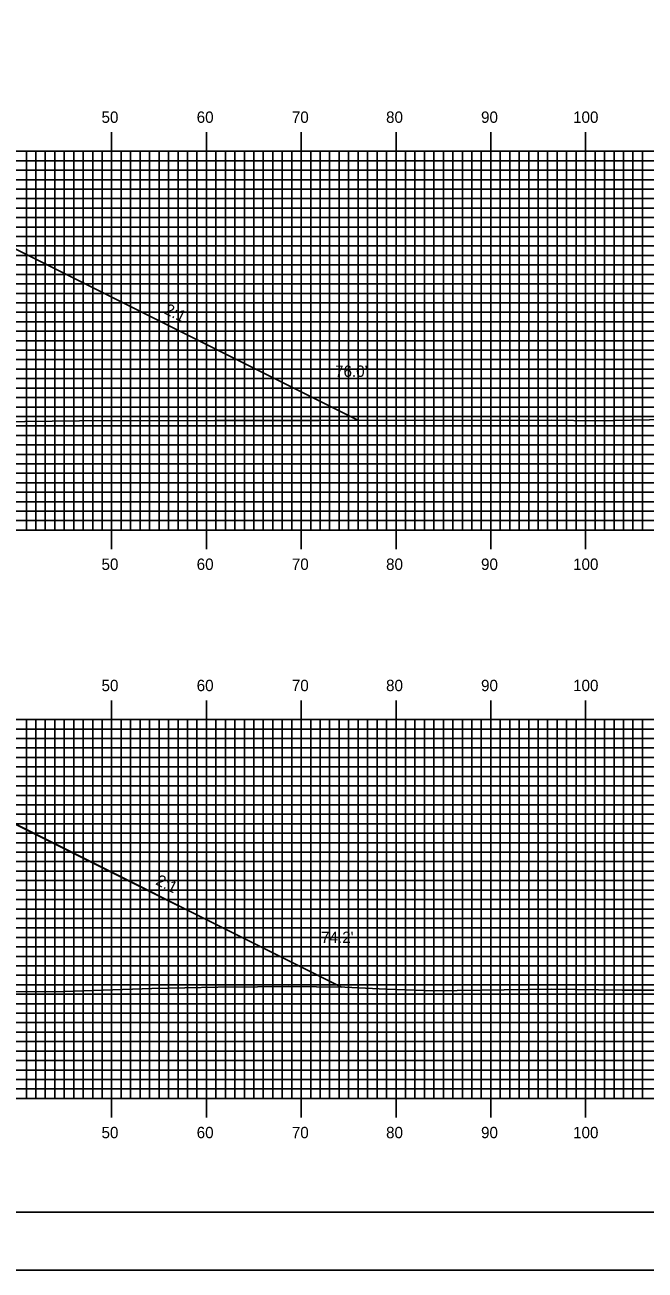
# Model space of a CAD drawing. Extents: x 1759036 to 1759380, y 442591 to 442811.
# Drawn here: x 1759243 to 1759308.4, y 442590.5 to 442722 of the extents above; entities that cross this region are included whole.
import ezdxf

# ---------------------------------------------------------------- set-up
doc = ezdxf.new("R2010")
doc.units = 0
for name, color, linetype in [('ANNOTATION', 7, 'Continuous'), ('BORDER', 7, 'Continuous'), ('D_Roadway_Centerline', 7, 'Continuous'), ('D_Roadway_SlopeLines', 7, 'Continuous'), ('D_Text_Standard', 7, 'Continuous'), ('H_V ANNOTATION', 7, 'Continuous'), ('MAJOR', 7, 'Continuous'), ('MINOR', 7, 'Continuous'), ('PLOT BOUNDARY', 7, 'Continuous'), ('S_Roadway_Centerline', 7, 'Continuous')]:
    doc.layers.add(name, color=color, linetype=linetype)

msp = doc.modelspace()

# ---------------------------------------------------------------- linework, layer by layer
at = {"layer": 'BORDER'}
msp.add_lwpolyline([(1759052.56, 442596.67), (1759372.56, 442596.67), (1759372.56, 442806.67), (1759052.56, 442806.67)], close=True, dxfattribs=at)
at = {"layer": 'D_Roadway_Centerline'}
for points in [[(1759138.72, 442679.79), (1759172.85, 442696.86), (1759178.14, 442699.51), (1759181.14, 442699.63), (1759189.14, 442699.95), (1759190.16, 442699.98), (1759202.16, 442700.41), (1759214.16, 442700.85), (1759226.16, 442701.21), (1759234.16, 442700.89), (1759237.16, 442700.77), (1759241.91, 442698.4), (1759278.21, 442680.25)], [(1759138.26, 442619.99), (1759170.85, 442636.29), (1759176.15, 442638.93), (1759179.15, 442639.05), (1759187.15, 442639.37), (1759190.16, 442639.48), (1759202.16, 442639.92), (1759214.16, 442640.35), (1759226.16, 442640.48), (1759234.16, 442640.16), (1759237.16, 442640.04), (1759241.91, 442637.66), (1759276.4, 442620.42)]]:
    msp.add_lwpolyline(points, dxfattribs=at)
at = {"layer": 'D_Roadway_SlopeLines'}
for points in [[(1759237.16, 442700.77), (1759278.21, 442680.25)], [(1759237.16, 442640.04), (1759276.4, 442620.42)]]:
    msp.add_lwpolyline(points, dxfattribs=at)
at = {"layer": 'MAJOR'}
for p, q in [((1759252.16, 442710.67), (1759252.16, 442708.67)), ((1759262.16, 442710.67), (1759262.16, 442708.67)), ((1759272.16, 442710.67), (1759272.16, 442708.67)), ((1759282.16, 442710.67), (1759282.16, 442708.67)), ((1759292.16, 442710.67), (1759292.16, 442708.67)), ((1759302.16, 442710.67), (1759302.16, 442708.67)), ((1759062.16, 442708.67), (1759342.16, 442708.67)), ((1759062.16, 442708.67), (1759342.16, 442708.67)), ((1759252.16, 442668.67), (1759252.16, 442708.67)), ((1759262.16, 442668.67), (1759262.16, 442708.67)), ((1759272.16, 442668.67), (1759272.16, 442708.67)), ((1759282.16, 442668.67), (1759282.16, 442708.67)), ((1759292.16, 442668.67), (1759292.16, 442708.67)), ((1759302.16, 442668.67), (1759302.16, 442708.67)), ((1759062.16, 442703.67), (1759342.16, 442703.67)), ((1759062.16, 442698.67), (1759342.16, 442698.67)), ((1759062.16, 442693.67), (1759342.16, 442693.67)), ((1759062.16, 442688.67), (1759342.16, 442688.67)), ((1759062.16, 442683.67), (1759342.16, 442683.67)), ((1759062.16, 442678.67), (1759342.16, 442678.67)), ((1759062.16, 442673.67), (1759342.16, 442673.67)), ((1759062.16, 442668.67), (1759342.16, 442668.67)), ((1759062.16, 442668.67), (1759342.16, 442668.67)), ((1759252.16, 442666.66), (1759252.16, 442668.67)), ((1759262.16, 442666.66), (1759262.16, 442668.67)), ((1759272.16, 442666.66), (1759272.16, 442668.67)), ((1759282.16, 442666.66), (1759282.16, 442668.67)), ((1759292.16, 442666.66), (1759292.16, 442668.67)), ((1759302.16, 442666.66), (1759302.16, 442668.67)), ((1759252.16, 442650.67), (1759252.16, 442648.67)), ((1759262.16, 442650.67), (1759262.16, 442648.67)), ((1759272.16, 442650.67), (1759272.16, 442648.67)), ((1759282.16, 442650.67), (1759282.16, 442648.67)), ((1759292.16, 442650.67), (1759292.16, 442648.67)), ((1759302.16, 442650.67), (1759302.16, 442648.67)), ((1759062.16, 442648.67), (1759342.16, 442648.67)), ((1759062.16, 442648.67), (1759342.16, 442648.67)), ((1759252.16, 442608.67), (1759252.16, 442648.67)), ((1759262.16, 442608.67), (1759262.16, 442648.67)), ((1759272.16, 442608.67), (1759272.16, 442648.67)), ((1759282.16, 442608.67), (1759282.16, 442648.67)), ((1759292.16, 442608.67), (1759292.16, 442648.67)), ((1759302.16, 442608.67), (1759302.16, 442648.67)), ((1759062.16, 442643.67), (1759342.16, 442643.67)), ((1759062.16, 442638.67), (1759342.16, 442638.67)), ((1759062.16, 442633.67), (1759342.16, 442633.67)), ((1759062.16, 442628.67), (1759342.16, 442628.67)), ((1759062.16, 442623.67), (1759342.16, 442623.67)), ((1759062.16, 442618.67), (1759342.16, 442618.67)), ((1759062.16, 442613.67), (1759342.16, 442613.67)), ((1759062.16, 442608.67), (1759342.16, 442608.67)), ((1759062.16, 442608.67), (1759342.16, 442608.67)), ((1759252.16, 442606.66), (1759252.16, 442608.67)), ((1759262.16, 442606.66), (1759262.16, 442608.67)), ((1759272.16, 442606.66), (1759272.16, 442608.67)), ((1759282.16, 442606.66), (1759282.16, 442608.67)), ((1759292.16, 442606.66), (1759292.16, 442608.67)), ((1759302.16, 442606.66), (1759302.16, 442608.67))]:
    msp.add_line(p, q, dxfattribs=at)
at = {"layer": 'MINOR'}
for p, q in [((1759243.16, 442668.67), (1759243.16, 442708.67)), ((1759244.16, 442668.67), (1759244.16, 442708.67)), ((1759245.16, 442668.67), (1759245.16, 442708.67)), ((1759246.16, 442668.67), (1759246.16, 442708.67)), ((1759247.16, 442668.67), (1759247.16, 442708.67)), ((1759248.16, 442668.67), (1759248.16, 442708.67)), ((1759249.16, 442668.67), (1759249.16, 442708.67)), ((1759250.16, 442668.67), (1759250.16, 442708.67)), ((1759251.16, 442668.67), (1759251.16, 442708.67)), ((1759253.16, 442668.67), (1759253.16, 442708.67)), ((1759254.16, 442668.67), (1759254.16, 442708.67)), ((1759255.16, 442668.67), (1759255.16, 442708.67)), ((1759256.16, 442668.67), (1759256.16, 442708.67)), ((1759257.16, 442668.67), (1759257.16, 442708.67)), ((1759258.16, 442668.67), (1759258.16, 442708.67)), ((1759259.16, 442668.67), (1759259.16, 442708.67)), ((1759260.16, 442668.67), (1759260.16, 442708.67)), ((1759261.16, 442668.67), (1759261.16, 442708.67)), ((1759263.16, 442668.67), (1759263.16, 442708.67)), ((1759264.16, 442668.67), (1759264.16, 442708.67)), ((1759265.16, 442668.67), (1759265.16, 442708.67)), ((1759266.16, 442668.67), (1759266.16, 442708.67)), ((1759267.16, 442668.67), (1759267.16, 442708.67)), ((1759268.16, 442668.67), (1759268.16, 442708.67)), ((1759269.16, 442668.67), (1759269.16, 442708.67)), ((1759270.16, 442668.67), (1759270.16, 442708.67)), ((1759271.16, 442668.67), (1759271.16, 442708.67)), ((1759273.16, 442668.67), (1759273.16, 442708.67)), ((1759274.16, 442668.67), (1759274.16, 442708.67)), ((1759275.16, 442668.67), (1759275.16, 442708.67)), ((1759276.16, 442668.67), (1759276.16, 442708.67)), ((1759277.16, 442668.67), (1759277.16, 442708.67)), ((1759278.16, 442668.67), (1759278.16, 442708.67)), ((1759279.16, 442668.67), (1759279.16, 442708.67)), ((1759280.16, 442668.67), (1759280.16, 442708.67)), ((1759281.16, 442668.67), (1759281.16, 442708.67)), ((1759283.16, 442668.67), (1759283.16, 442708.67)), ((1759284.16, 442668.67), (1759284.16, 442708.67)), ((1759285.16, 442668.67), (1759285.16, 442708.67)), ((1759286.16, 442668.67), (1759286.16, 442708.67)), ((1759287.16, 442668.67), (1759287.16, 442708.67)), ((1759288.16, 442668.67), (1759288.16, 442708.67)), ((1759289.16, 442668.67), (1759289.16, 442708.67)), ((1759290.16, 442668.67), (1759290.16, 442708.67)), ((1759291.16, 442668.67), (1759291.16, 442708.67)), ((1759293.16, 442668.67), (1759293.16, 442708.67)), ((1759294.16, 442668.67), (1759294.16, 442708.67)), ((1759295.16, 442668.67), (1759295.16, 442708.67)), ((1759296.16, 442668.67), (1759296.16, 442708.67)), ((1759297.16, 442668.67), (1759297.16, 442708.67)), ((1759298.16, 442668.67), (1759298.16, 442708.67)), ((1759299.16, 442668.67), (1759299.16, 442708.67)), ((1759300.16, 442668.67), (1759300.16, 442708.67)), ((1759301.16, 442668.67), (1759301.16, 442708.67)), ((1759303.16, 442668.67), (1759303.16, 442708.67)), ((1759304.16, 442668.67), (1759304.16, 442708.67)), ((1759305.16, 442668.67), (1759305.16, 442708.67)), ((1759306.16, 442668.67), (1759306.16, 442708.67)), ((1759307.16, 442668.67), (1759307.16, 442708.67)), ((1759308.16, 442668.67), (1759308.16, 442708.67)), ((1759062.16, 442707.67), (1759342.16, 442707.67)), ((1759062.16, 442706.67), (1759342.16, 442706.67)), ((1759062.16, 442705.67), (1759342.16, 442705.67)), ((1759062.16, 442704.67), (1759342.16, 442704.67)), ((1759062.16, 442702.67), (1759342.16, 442702.67)), ((1759062.16, 442701.67), (1759342.16, 442701.67)), ((1759062.16, 442700.67), (1759342.16, 442700.67)), ((1759062.16, 442699.67), (1759342.16, 442699.67)), ((1759062.16, 442697.67), (1759342.16, 442697.67)), ((1759062.16, 442696.67), (1759342.16, 442696.67)), ((1759062.16, 442695.67), (1759342.16, 442695.67)), ((1759062.16, 442694.67), (1759342.16, 442694.67)), ((1759062.16, 442692.67), (1759342.16, 442692.67)), ((1759062.16, 442691.67), (1759342.16, 442691.67)), ((1759062.16, 442690.67), (1759342.16, 442690.67)), ((1759062.16, 442689.67), (1759342.16, 442689.67)), ((1759062.16, 442687.67), (1759342.16, 442687.67)), ((1759062.16, 442686.67), (1759342.16, 442686.67)), ((1759062.16, 442685.67), (1759342.16, 442685.67)), ((1759062.16, 442684.67), (1759342.16, 442684.67)), ((1759062.16, 442682.67), (1759342.16, 442682.67)), ((1759062.16, 442681.67), (1759342.16, 442681.67)), ((1759062.16, 442680.67), (1759342.16, 442680.67)), ((1759062.16, 442679.67), (1759342.16, 442679.67)), ((1759062.16, 442677.67), (1759342.16, 442677.67)), ((1759062.16, 442676.67), (1759342.16, 442676.67)), ((1759062.16, 442675.67), (1759342.16, 442675.67)), ((1759062.16, 442674.67), (1759342.16, 442674.67)), ((1759062.16, 442672.67), (1759342.16, 442672.67)), ((1759062.16, 442671.67), (1759342.16, 442671.67)), ((1759062.16, 442670.67), (1759342.16, 442670.67)), ((1759062.16, 442669.67), (1759342.16, 442669.67)), ((1759062.16, 442647.67), (1759342.16, 442647.67)), ((1759243.16, 442608.67), (1759243.16, 442648.67)), ((1759244.16, 442608.67), (1759244.16, 442648.67)), ((1759245.16, 442608.67), (1759245.16, 442648.67)), ((1759246.16, 442608.67), (1759246.16, 442648.67)), ((1759247.16, 442608.67), (1759247.16, 442648.67)), ((1759248.16, 442608.67), (1759248.16, 442648.67)), ((1759249.16, 442608.67), (1759249.16, 442648.67)), ((1759250.16, 442608.67), (1759250.16, 442648.67)), ((1759251.16, 442608.67), (1759251.16, 442648.67)), ((1759253.16, 442608.67), (1759253.16, 442648.67)), ((1759254.16, 442608.67), (1759254.16, 442648.67)), ((1759255.16, 442608.67), (1759255.16, 442648.67)), ((1759256.16, 442608.67), (1759256.16, 442648.67)), ((1759257.16, 442608.67), (1759257.16, 442648.67)), ((1759258.16, 442608.67), (1759258.16, 442648.67)), ((1759259.16, 442608.67), (1759259.16, 442648.67)), ((1759260.16, 442608.67), (1759260.16, 442648.67)), ((1759261.16, 442608.67), (1759261.16, 442648.67)), ((1759263.16, 442608.67), (1759263.16, 442648.67)), ((1759264.16, 442608.67), (1759264.16, 442648.67)), ((1759265.16, 442608.67), (1759265.16, 442648.67)), ((1759266.16, 442608.67), (1759266.16, 442648.67)), ((1759267.16, 442608.67), (1759267.16, 442648.67)), ((1759268.16, 442608.67), (1759268.16, 442648.67)), ((1759269.16, 442608.67), (1759269.16, 442648.67)), ((1759270.16, 442608.67), (1759270.16, 442648.67)), ((1759271.16, 442608.67), (1759271.16, 442648.67)), ((1759273.16, 442608.67), (1759273.16, 442648.67)), ((1759274.16, 442608.67), (1759274.16, 442648.67)), ((1759275.16, 442608.67), (1759275.16, 442648.67)), ((1759276.16, 442608.67), (1759276.16, 442648.67)), ((1759277.16, 442608.67), (1759277.16, 442648.67)), ((1759278.16, 442608.67), (1759278.16, 442648.67)), ((1759279.16, 442608.67), (1759279.16, 442648.67)), ((1759280.16, 442608.67), (1759280.16, 442648.67)), ((1759281.16, 442608.67), (1759281.16, 442648.67)), ((1759283.16, 442608.67), (1759283.16, 442648.67)), ((1759284.16, 442608.67), (1759284.16, 442648.67)), ((1759285.16, 442608.67), (1759285.16, 442648.67)), ((1759286.16, 442608.67), (1759286.16, 442648.67)), ((1759287.16, 442608.67), (1759287.16, 442648.67)), ((1759288.16, 442608.67), (1759288.16, 442648.67)), ((1759289.16, 442608.67), (1759289.16, 442648.67)), ((1759290.16, 442608.67), (1759290.16, 442648.67)), ((1759291.16, 442608.67), (1759291.16, 442648.67)), ((1759293.16, 442608.67), (1759293.16, 442648.67)), ((1759294.16, 442608.67), (1759294.16, 442648.67)), ((1759295.16, 442608.67), (1759295.16, 442648.67)), ((1759296.16, 442608.67), (1759296.16, 442648.67)), ((1759297.16, 442608.67), (1759297.16, 442648.67)), ((1759298.16, 442608.67), (1759298.16, 442648.67)), ((1759299.16, 442608.67), (1759299.16, 442648.67)), ((1759300.16, 442608.67), (1759300.16, 442648.67)), ((1759301.16, 442608.67), (1759301.16, 442648.67)), ((1759303.16, 442608.67), (1759303.16, 442648.67)), ((1759304.16, 442608.67), (1759304.16, 442648.67)), ((1759305.16, 442608.67), (1759305.16, 442648.67)), ((1759306.16, 442608.67), (1759306.16, 442648.67)), ((1759307.16, 442608.67), (1759307.16, 442648.67)), ((1759308.16, 442608.67), (1759308.16, 442648.67)), ((1759062.16, 442646.67), (1759342.16, 442646.67)), ((1759062.16, 442645.67), (1759342.16, 442645.67)), ((1759062.16, 442644.67), (1759342.16, 442644.67)), ((1759062.16, 442642.67), (1759342.16, 442642.67)), ((1759062.16, 442641.67), (1759342.16, 442641.67)), ((1759062.16, 442640.67), (1759342.16, 442640.67)), ((1759062.16, 442639.67), (1759342.16, 442639.67)), ((1759062.16, 442637.67), (1759342.16, 442637.67)), ((1759062.16, 442636.67), (1759342.16, 442636.67)), ((1759062.16, 442635.67), (1759342.16, 442635.67)), ((1759062.16, 442634.67), (1759342.16, 442634.67)), ((1759062.16, 442632.67), (1759342.16, 442632.67)), ((1759062.16, 442631.67), (1759342.16, 442631.67)), ((1759062.16, 442630.67), (1759342.16, 442630.67)), ((1759062.16, 442629.67), (1759342.16, 442629.67)), ((1759062.16, 442627.67), (1759342.16, 442627.67)), ((1759062.16, 442626.67), (1759342.16, 442626.67)), ((1759062.16, 442625.67), (1759342.16, 442625.67)), ((1759062.16, 442624.67), (1759342.16, 442624.67)), ((1759062.16, 442622.67), (1759342.16, 442622.67)), ((1759062.16, 442621.67), (1759342.16, 442621.67)), ((1759062.16, 442620.67), (1759342.16, 442620.67)), ((1759062.16, 442619.67), (1759342.16, 442619.67)), ((1759062.16, 442617.67), (1759342.16, 442617.67)), ((1759062.16, 442616.67), (1759342.16, 442616.67)), ((1759062.16, 442615.67), (1759342.16, 442615.67)), ((1759062.16, 442614.67), (1759342.16, 442614.67)), ((1759062.16, 442612.67), (1759342.16, 442612.67)), ((1759062.16, 442611.67), (1759342.16, 442611.67)), ((1759062.16, 442610.67), (1759342.16, 442610.67)), ((1759062.16, 442609.67), (1759342.16, 442609.67))]:
    msp.add_line(p, q, dxfattribs=at)
at = {"layer": 'PLOT BOUNDARY'}
msp.add_lwpolyline([(1759036.37, 442590.55), (1759376.37, 442590.55), (1759376.37, 442810.55), (1759036.37, 442810.55)], close=True, dxfattribs=at)
at = {"layer": 'S_Roadway_Centerline'}
for points in [[(1759232.15, 442679.87), (1759243.01, 442680.13), (1759248.75, 442680.22), (1759263.06, 442680.24), (1759270.52, 442680.23), (1759274.03, 442680.25), (1759298.56, 442680.27), (1759303.25, 442680.22), (1759305.08, 442680.23), (1759314.63, 442680.42), (1759315.58, 442680.43), (1759325.85, 442680.31), (1759326.2, 442680.36), (1759326.32, 442680.31), (1759330.55, 442680.76), (1759331.96, 442680.45), (1759332.11, 442680.41), (1759332.91, 442680.32), (1759335.29, 442679.67), (1759341.26, 442678.25), (1759341.54, 442678.2), (1759342.16, 442678.1)], [(1759236.55, 442619.93), (1759247.16, 442619.97), (1759256.41, 442620.29), (1759263.35, 442620.41), (1759267.55, 442620.46), (1759270.78, 442620.48), (1759276.75, 442620.42), (1759281.12, 442620.21), (1759286.12, 442620.04), (1759298.57, 442620.19), (1759306.02, 442620.11), (1759314.02, 442620.1)]]:
    msp.add_lwpolyline(points, dxfattribs=at)

# ---------------------------------------------------------------- texts
at = {"layer": 'ANNOTATION'}
for p in [(1759257.62, 442691.58), (1759256.72, 442631.3)]:
    msp.add_text('2:1', height=1.2, rotation=333.4349, dxfattribs=at).set_placement(p)
at = {"layer": 'D_Text_Standard'}
for s, p in [("76.0'", (1759275.73, 442684.85)), ("74.2'", (1759274.25, 442625.08))]:
    msp.add_text(s, height=1.2, dxfattribs=at).set_placement(p)
at = {"layer": 'H_V ANNOTATION'}
for s, p in [('50', (1759251.09, 442711.67)), ('60', (1759261.13, 442711.67)), ('70', (1759271.17, 442711.67)), ('80', (1759281.11, 442711.67)), ('90', (1759291.13, 442711.67)), ('100', (1759300.84, 442711.67)), ('50', (1759251.09, 442664.47)), ('60', (1759261.13, 442664.47)), ('70', (1759271.17, 442664.47)), ('80', (1759281.11, 442664.47)), ('90', (1759291.13, 442664.47)), ('100', (1759300.84, 442664.47)), ('50', (1759251.09, 442651.67)), ('60', (1759261.13, 442651.67)), ('70', (1759271.17, 442651.67)), ('80', (1759281.11, 442651.67)), ('90', (1759291.13, 442651.67)), ('100', (1759300.84, 442651.67)), ('50', (1759251.09, 442604.47)), ('60', (1759261.13, 442604.47)), ('70', (1759271.17, 442604.47)), ('80', (1759281.11, 442604.47)), ('90', (1759291.13, 442604.47)), ('100', (1759300.84, 442604.47))]:
    msp.add_text(s, height=1.2, dxfattribs=at).set_placement(p)

doc.saveas('drawing.dxf')
